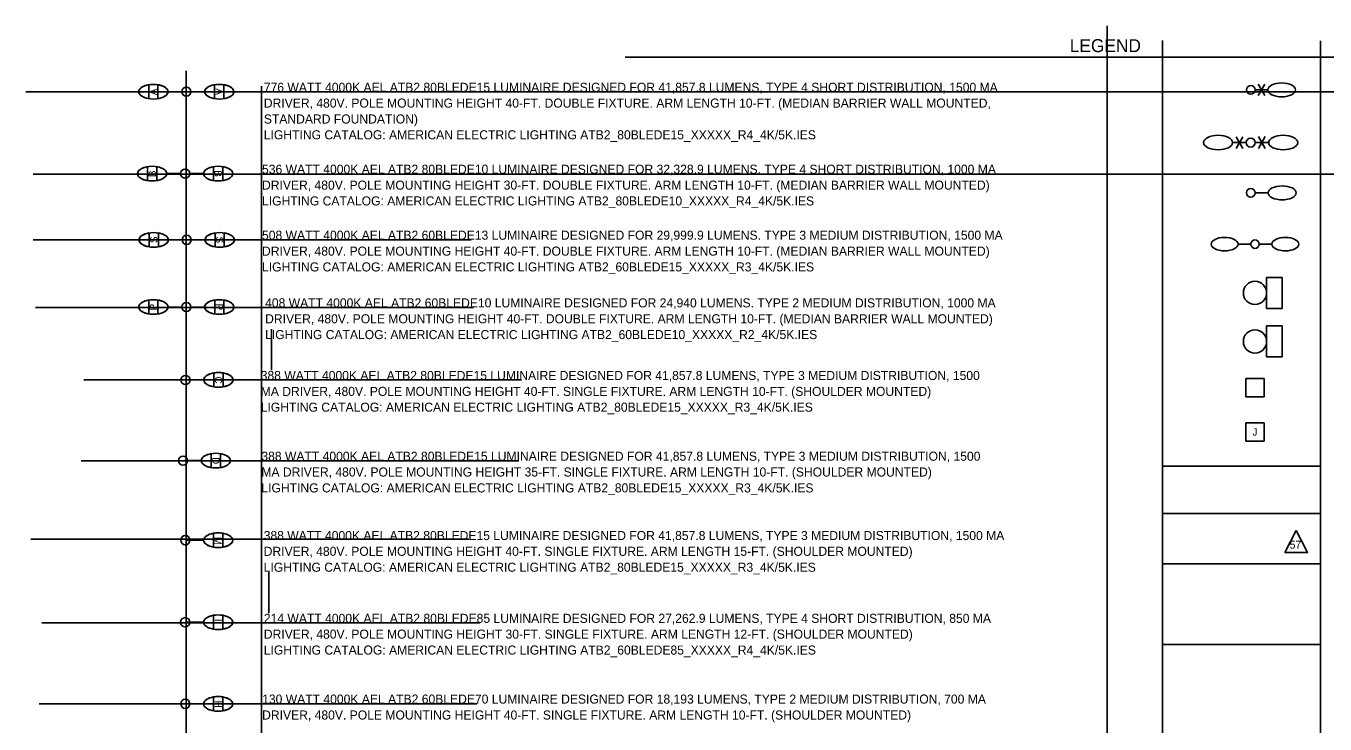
# Model space of a CAD drawing. Extents: x -0.7 to 15.2, y -0.9 to 9.6.
# Drawn here: x -0.65 to 9.38, y 4.21 to 9.6 of the extents above; entities that cross this region are included whole.
import ezdxf

# ---------------------------------------------------------------- set-up
doc = ezdxf.new("R2010")
doc.units = 0
for name, color, linetype in [('ActivePointCell_dp', 7, 'Continuous'), ('AdhocPoint_dp', 7, 'Continuous'), ('Cloud_dp', 7, 'Continuous'), ('Conduit', 7, 'Continuous'), ('JunctBoxA', 7, 'Continuous'), ('LiteCond_ep', 7, 'Continuous'), ('LoadCenter', 7, 'Continuous'), ('LoadCenter_ep', 7, 'Continuous'), ('Miscellaneous1', 7, 'Continuous'), ('Miscellaneous2', 7, 'Continuous'), ('Miscellaneous7', 7, 'Continuous'), ('PoleLight_ep', 7, 'Continuous'), ('ScratchEle_dp', 7, 'Continuous'), ('TextShtNo', 7, 'Continuous'), ('TextTitle', 7, 'Continuous')]:
    doc.layers.add(name, color=color, linetype=linetype)

msp = doc.modelspace()

# ---------------------------------------------------------------- linework, layer by layer
at = {"layer": 'ActivePointCell_dp'}
for p, q in [((7.7, -0.9), (7.7, 9.6)), ((8.126, 9.487), (8.126, 0.725)), ((9.347, 9.484), (9.347, 0.722)), ((0.584, 9.253), (0.584, 0.037)), ((1.164, 0.128), (1.164, 9.134)), ((14.876, 9.092), (-0.655, 9.092)), ((0.584, 9.092), (0.584, 6.27)), ((14.867, 8.456), (-0.599, 8.456)), ((2.784, 7.946), (-0.599, 7.946)), ((2.802, 7.424), (-0.582, 7.424)), ((1.241, 6.941), (1.241, 7.258)), ((3.174, 6.864), (-0.209, 6.864)), ((3.154, 6.24), (-0.229, 6.24)), ((2.766, 5.634), (-0.617, 5.634)), ((1.221, 5.062), (1.221, 5.379)), ((2.853, 4.986), (-0.531, 4.986)), ((2.83, 4.36), (-0.553, 4.36))]:
    msp.add_line(p, q, dxfattribs=at)
at = {"layer": 'Cloud_dp'}
msp.add_lwpolyline([(9.16, 5.7), (9.072, 5.531), (9.248, 5.531)], close=True, dxfattribs=at)
at = {"layer": 'Conduit'}
msp.add_line((8.126, 6.199), (9.347, 6.199), dxfattribs=at)
at = {"layer": 'LiteCond_ep'}
msp.add_line((8.126, 5.831), (9.347, 5.831), dxfattribs=at)
at = {"layer": 'LoadCenter'}
for p, q in [((8.931, 7.042), (8.931, 7.282)), ((8.931, 7.282), (9.051, 7.282)), ((9.051, 7.282), (9.051, 7.042)), ((9.051, 7.042), (8.931, 7.042))]:
    msp.add_line(p, q, dxfattribs=at)
msp.add_circle((8.841, 7.162), 0.09, dxfattribs=at)
at = {"layer": 'LoadCenter_ep'}
for p, q in [((8.931, 7.417), (8.931, 7.657)), ((8.931, 7.657), (9.051, 7.657)), ((9.051, 7.657), (9.051, 7.417)), ((9.051, 7.417), (8.931, 7.417))]:
    msp.add_line(p, q, dxfattribs=at)
msp.add_circle((8.841, 7.537), 0.09, dxfattribs=at)
at = {"layer": 'Miscellaneous1'}
msp.add_line((8.121, 5.443), (9.343, 5.443), dxfattribs=at)
at = {"layer": 'Miscellaneous2'}
for centre in [(0.832, 6.865), (0.812, 6.241), (0.83, 5.626), (0.83, 4.992), (0.83, 4.361)]:
    msp.add_ellipse(centre, major_axis=(-0.113, 0), ratio=0.5, start_param=4.391241, end_param=4.391271, dxfattribs=at)
at = {"layer": 'Miscellaneous7'}
msp.add_line((8.125, 4.821), (9.343, 4.821), dxfattribs=at)
at = {"layer": 'PoleLight_ep'}
for p, q in [((8.916, 9.063), (8.866, 9.149)), ((8.916, 9.149), (8.866, 9.063)), ((8.841, 9.106), (8.941, 9.106)), ((8.695, 8.653), (8.748, 8.744)), ((8.695, 8.744), (8.748, 8.653)), ((8.92, 8.745), (8.868, 8.654)), ((8.92, 8.654), (8.868, 8.745)), ((8.773, 8.699), (8.668, 8.699)), ((8.843, 8.699), (8.947, 8.699)), ((8.841, 8.31), (8.943, 8.31)), ((8.808, 7.914), (8.71, 7.914)), ((8.873, 7.914), (8.971, 7.914))]:
    msp.add_line(p, q, dxfattribs=at)
for centre, radius in [((8.808, 9.106), 0.0333), ((8.808, 8.699), 0.0349), ((8.808, 8.31), 0.0338), ((8.841, 7.914), 0.0326)]:
    msp.add_circle(centre, radius, dxfattribs=at)
for centre, major_axis in [((9.047, 9.106), (0.107, 0)), ((8.556, 8.699), (-0.112, 0)), ((9.059, 8.699), (0.112, 0)), ((9.051, 8.31), (0.108, 0)), ((8.606, 7.914), (-0.104, 0)), ((9.076, 7.914), (0.104, 0))]:
    msp.add_ellipse(centre, major_axis=major_axis, ratio=0.5, dxfattribs=at)
at = {"layer": 'ScratchEle_dp'}
for p, q in [((0.294, 9.038), (0.294, 9.145)), ((0.365, 9.145), (0.365, 9.038)), ((0.803, 9.038), (0.803, 9.145)), ((0.875, 9.145), (0.875, 9.038)), ((0.549, 9.092), (0.443, 9.092)), ((0.62, 9.092), (0.726, 9.092)), ((0.285, 8.405), (0.285, 8.512)), ((0.356, 8.512), (0.356, 8.405)), ((0.54, 8.459), (0.434, 8.459)), ((0.611, 8.459), (0.717, 8.459)), ((0.794, 8.405), (0.794, 8.512)), ((0.866, 8.512), (0.866, 8.405)), ((0.296, 7.894), (0.296, 8.001)), ((0.368, 8.001), (0.368, 7.894)), ((0.551, 7.947), (0.445, 7.947)), ((0.622, 7.947), (0.728, 7.947)), ((0.806, 7.894), (0.806, 8.001)), ((0.877, 8.001), (0.877, 7.894)), ((0.294, 7.374), (0.294, 7.482)), ((0.365, 7.482), (0.365, 7.374)), ((0.549, 7.428), (0.443, 7.428)), ((0.62, 7.428), (0.726, 7.428)), ((0.804, 7.374), (0.804, 7.482)), ((0.875, 7.482), (0.875, 7.374)), ((0.593, 6.864), (0.724, 6.864)), ((0.797, 6.811), (0.797, 6.918)), ((0.797, 6.917), (0.797, 6.811)), ((0.868, 6.918), (0.868, 6.811)), ((0.868, 6.811), (0.868, 6.918)), ((0.573, 6.241), (0.704, 6.241)), ((0.777, 6.187), (0.777, 6.295)), ((0.777, 6.294), (0.777, 6.187)), ((0.848, 6.295), (0.848, 6.187)), ((0.848, 6.187), (0.848, 6.295)), ((0.591, 5.626), (0.722, 5.626)), ((0.794, 5.572), (0.794, 5.68)), ((0.794, 5.679), (0.794, 5.572)), ((0.866, 5.68), (0.866, 5.572)), ((0.866, 5.572), (0.866, 5.68)), ((0.794, 4.938), (0.794, 5.046)), ((0.794, 5.045), (0.794, 4.938)), ((0.865, 5.046), (0.865, 4.938)), ((0.865, 4.938), (0.865, 5.046)), ((0.59, 4.992), (0.721, 4.992)), ((0.591, 4.361), (0.722, 4.361)), ((0.795, 4.307), (0.795, 4.415)), ((0.795, 4.413), (0.795, 4.307)), ((0.866, 4.415), (0.866, 4.307)), ((0.866, 4.307), (0.866, 4.415))]:
    msp.add_line(p, q, dxfattribs=at)
for centre in [(0.584, 9.092), (0.584, 9.092), (0.575, 8.459), (0.575, 8.459), (0.587, 7.947), (0.587, 7.947), (0.584, 7.428), (0.584, 7.428), (0.578, 6.864), (0.578, 6.864), (0.558, 6.241), (0.558, 6.241), (0.576, 5.626), (0.576, 5.626), (0.575, 4.992), (0.575, 4.992), (0.576, 4.361), (0.576, 4.361)]:
    msp.add_circle(centre, 0.0354, dxfattribs=at)
for centre, major_axis in [((0.33, 9.092), (0.113, 0)), ((0.839, 9.092), (0.113, 0)), ((0.32, 8.459), (0.113, 0)), ((0.83, 8.459), (0.113, 0)), ((0.332, 7.947), (0.113, 0)), ((0.842, 7.947), (0.113, 0)), ((0.33, 7.428), (0.113, 0)), ((0.839, 7.428), (0.113, 0)), ((0.832, 6.865), (-0.113, 0)), ((0.812, 6.241), (-0.113, 0)), ((0.83, 5.626), (-0.113, 0)), ((0.83, 4.992), (-0.113, 0)), ((0.83, 4.361), (-0.113, 0))]:
    msp.add_ellipse(centre, major_axis=major_axis, ratio=0.5, dxfattribs=at)
for centre, major_axis, start_param, end_param in [((0.33, 9.092), (0.113, 0), 1.891945, 4.391241), ((0.33, 9.092), (0.113, 0), 0.847605, 1.249648), ((0.33, 9.092), (0.113, 0), 0, 0.847605), ((0.839, 9.092), (0.113, 0), 1.891945, 4.391241), ((0.839, 9.092), (0.113, 0), 0.847605, 1.249648), ((0.839, 9.092), (0.113, 0), 0, 0.847605), ((0.33, 9.092), (0.113, 0), 5.033538, 6.283185), ((0.839, 9.092), (0.113, 0), 5.033538, 6.283185), ((0.32, 8.459), (0.113, 0), 1.891945, 4.391241), ((0.32, 8.459), (0.113, 0), 0.847605, 1.249648), ((0.32, 8.459), (0.113, 0), 5.033538, 6.283185), ((0.32, 8.459), (0.113, 0), 0, 0.847605), ((0.83, 8.459), (0.113, 0), 1.891945, 4.391241), ((0.83, 8.459), (0.113, 0), 0.847605, 1.249648), ((0.83, 8.459), (0.113, 0), 5.033538, 6.283185), ((0.83, 8.459), (0.113, 0), 0, 0.847605), ((0.332, 7.947), (0.113, 0), 1.891945, 4.391241), ((0.332, 7.947), (0.113, 0), 0.847605, 1.249648), ((0.332, 7.947), (0.113, 0), 5.033538, 6.283185), ((0.332, 7.947), (0.113, 0), 0, 0.847605), ((0.842, 7.947), (0.113, 0), 1.891945, 4.391241), ((0.842, 7.947), (0.113, 0), 0.847605, 1.249648), ((0.842, 7.947), (0.113, 0), 5.033538, 6.283185), ((0.842, 7.947), (0.113, 0), 0, 0.847605), ((0.33, 7.428), (0.113, 0), 1.891945, 4.391241), ((0.33, 7.428), (0.113, 0), 0.847605, 1.249648), ((0.33, 7.428), (0.113, 0), 5.033538, 6.283185), ((0.33, 7.428), (0.113, 0), 0, 0.847605), ((0.839, 7.428), (0.113, 0), 1.891945, 4.391241), ((0.839, 7.428), (0.113, 0), 0.847605, 1.249648), ((0.839, 7.428), (0.113, 0), 5.033538, 6.283185), ((0.839, 7.428), (0.113, 0), 0, 0.847605), ((0.832, 6.865), (-0.113, 0), 5.033538, 6.283185), ((0.832, 6.865), (-0.113, 0), 0, 0.847605), ((0.832, 6.865), (-0.113, 0), 4.391271, 5.033538), ((0.832, 6.865), (-0.113, 0), 1.891945, 4.391241), ((0.832, 6.865), (-0.113, 0), 0.847605, 1.249648), ((0.832, 6.865), (-0.113, 0), 1.249648, 1.891946), ((0.812, 6.241), (-0.113, 0), 5.033538, 6.283185), ((0.812, 6.241), (-0.113, 0), 0, 0.847605), ((0.812, 6.241), (-0.113, 0), 4.391271, 5.033538), ((0.812, 6.241), (-0.113, 0), 1.891945, 4.391241), ((0.812, 6.241), (-0.113, 0), 0.847605, 1.249648), ((0.812, 6.241), (-0.113, 0), 1.249648, 1.891946), ((0.83, 5.626), (-0.113, 0), 5.033538, 6.283185), ((0.83, 5.626), (-0.113, 0), 0, 0.847605), ((0.83, 5.626), (-0.113, 0), 4.391271, 5.033538), ((0.83, 5.626), (-0.113, 0), 1.891945, 4.391241), ((0.83, 5.626), (-0.113, 0), 0.847605, 1.249648), ((0.83, 4.992), (-0.113, 0), 5.033538, 6.283185), ((0.83, 4.992), (-0.113, 0), 4.391271, 5.033538), ((0.83, 4.992), (-0.113, 0), 1.891945, 4.391241), ((0.83, 4.992), (-0.113, 0), 0, 0.847605), ((0.83, 4.992), (-0.113, 0), 0.847605, 1.249648), ((0.83, 4.992), (-0.113, 0), 1.249648, 1.891946), ((0.83, 4.361), (-0.113, 0), 4.391271, 5.033538), ((0.83, 4.361), (-0.113, 0), 5.033538, 6.283185), ((0.83, 4.361), (-0.113, 0), 0, 0.847605), ((0.83, 4.361), (-0.113, 0), 0.847605, 1.249648), ((0.83, 4.361), (-0.113, 0), 1.891945, 4.391241), ((0.83, 4.361), (-0.113, 0), 1.249648, 1.891946)]:
    msp.add_ellipse(centre, major_axis=major_axis, ratio=0.5, start_param=start_param, end_param=end_param, dxfattribs=at)
at = {"layer": 'TextShtNo'}
msp.add_line((3.976, 9.358), (12.03, 9.358), dxfattribs=at)
at = {"layer": 'TextTitle'}
for p, q in [((8.77, 6.734), (8.77, 6.875)), ((8.77, 6.875), (8.911, 6.875)), ((8.911, 6.875), (8.911, 6.734)), ((8.911, 6.734), (8.77, 6.734)), ((8.77, 6.533), (8.911, 6.533)), ((8.77, 6.392), (8.77, 6.533)), ((8.911, 6.533), (8.911, 6.392)), ((8.911, 6.392), (8.77, 6.392))]:
    msp.add_line(p, q, dxfattribs=at)

# ---------------------------------------------------------------- texts
at = {"layer": 'AdhocPoint_dp'}
for s, height, p in [('LEGEND', 0.1, (7.41, 9.398)), ('776 WATT 4000K AEL ATB2 80BLEDE15 LUMINAIRE DESIGNED FOR 41,857.8 LUMENS, TYPE 4 SHORT DISTRIBUTION, 1500 MA ', 0.07, (1.183, 9.091)), ('DRIVER, 480V. POLE MOUNTING HEIGHT 40-FT. DOUBLE FIXTURE. ARM LENGTH 10-FT. (MEDIAN BARRIER WALL MOUNTED, ', 0.07, (1.183, 8.969)), ('STANDARD FOUNDATION)', 0.07, (1.183, 8.846)), ('LIGHTING CATALOG: AMERICAN ELECTRIC LIGHTING ATB2_80BLEDE15_XXXXX_R4_4K/5K.IES', 0.07, (1.183, 8.724)), ('536 WATT 4000K AEL ATB2 80BLEDE10 LUMINAIRE DESIGNED FOR 32,328.9 LUMENS. TYPE 4 SHORT DISTRIBUTION, 1000 MA ', 0.07, (1.169, 8.458)), ('DRIVER, 480V. POLE MOUNTING HEIGHT 30-FT. DOUBLE FIXTURE. ARM LENGTH 10-FT. (MEDIAN BARRIER WALL MOUNTED)', 0.07, (1.169, 8.335)), ('LIGHTING CATALOG: AMERICAN ELECTRIC LIGHTING ATB2_80BLEDE10_XXXXX_R4_4K/5K.IES', 0.07, (1.169, 8.213)), ('508 WATT 4000K AEL ATB2 60BLEDE13 LUMINAIRE DESIGNED FOR 29,999.9 LUMENS. TYPE 3 MEDIUM DISTRIBUTION, 1500 MA ', 0.07, (1.169, 7.948)), ('DRIVER, 480V. POLE MOUNTING HEIGHT 40-FT. DOUBLE FIXTURE. ARM LENGTH 10-FT. (MEDIAN BARRIER WALL MOUNTED)', 0.07, (1.169, 7.825)), ('LIGHTING CATALOG: AMERICAN ELECTRIC LIGHTING ATB2_60BLEDE15_XXXXX_R3_4K/5K.IES', 0.07, (1.169, 7.703)), ('408 WATT 4000K AEL ATB2 60BLEDE10 LUMINAIRE DESIGNED FOR 24,940 LUMENS. TYPE 2 MEDIUM DISTRIBUTION, 1000 MA ', 0.07, (1.193, 7.425)), ('DRIVER, 480V. POLE MOUNTING HEIGHT 40-FT. DOUBLE FIXTURE. ARM LENGTH 10-FT. (MEDIAN BARRIER WALL MOUNTED)', 0.07, (1.193, 7.302)), ('LIGHTING CATALOG: AMERICAN ELECTRIC LIGHTING ATB2_60BLEDE10_XXXXX_R2_4K/5K.IES', 0.07, (1.193, 7.18)), ('388 WATT 4000K AEL ATB2 80BLEDE15 LUMINAIRE DESIGNED FOR 41,857.8 LUMENS, TYPE 3 MEDIUM DISTRIBUTION, 1500 ', 0.07, (1.159, 6.864)), ('MA DRIVER, 480V. POLE MOUNTING HEIGHT 40-FT. SINGLE FIXTURE. ARM LENGTH 10-FT. (SHOULDER MOUNTED)', 0.07, (1.159, 6.741)), ('LIGHTING CATALOG: AMERICAN ELECTRIC LIGHTING ATB2_80BLEDE15_XXXXX_R3_4K/5K.IES', 0.07, (1.159, 6.619)), ('388 WATT 4000K AEL ATB2 80BLEDE15 LUMINAIRE DESIGNED FOR 41,857.8 LUMENS, TYPE 3 MEDIUM DISTRIBUTION, 1500 ', 0.07, (1.164, 6.24)), ('MA DRIVER, 480V. POLE MOUNTING HEIGHT 35-FT. SINGLE FIXTURE. ARM LENGTH 10-FT. (SHOULDER MOUNTED)', 0.07, (1.164, 6.118)), ('LIGHTING CATALOG: AMERICAN ELECTRIC LIGHTING ATB2_80BLEDE15_XXXXX_R3_4K/5K.IES', 0.07, (1.164, 5.995)), ('388 WATT 4000K AEL ATB2 80BLEDE15 LUMINAIRE DESIGNED FOR 41,857.8 LUMENS, TYPE 3 MEDIUM DISTRIBUTION, 1500 MA ', 0.07, (1.182, 5.627)), ('DRIVER, 480V. POLE MOUNTING HEIGHT 40-FT. SINGLE FIXTURE. ARM LENGTH 15-FT. (SHOULDER MOUNTED)', 0.07, (1.182, 5.505)), ('LIGHTING CATALOG: AMERICAN ELECTRIC LIGHTING ATB2_80BLEDE15_XXXXX_R3_4K/5K.IES', 0.07, (1.182, 5.382)), ('214 WATT 4000K AEL ATB2 80BLEDE85 LUMINAIRE DESIGNED FOR 27,262.9 LUMENS, TYPE 4 SHORT DISTRIBUTION, 850 MA ', 0.07, (1.183, 4.987)), ('DRIVER, 480V. POLE MOUNTING HEIGHT 30-FT. SINGLE FIXTURE. ARM LENGTH 12-FT. (SHOULDER MOUNTED)', 0.07, (1.183, 4.865)), ('LIGHTING CATALOG: AMERICAN ELECTRIC LIGHTING ATB2_60BLEDE85_XXXXX_R4_4K/5K.IES', 0.07, (1.183, 4.742)), ('130 WATT 4000K AEL ATB2 60BLEDE70 LUMINAIRE DESIGNED FOR 18,193 LUMENS, TYPE 2 MEDIUM DISTRIBUTION, 700 MA ', 0.07, (1.17, 4.363)), ('DRIVER, 480V. POLE MOUNTING HEIGHT 40-FT. SINGLE FIXTURE. ARM LENGTH 10-FT. (SHOULDER MOUNTED)', 0.07, (1.17, 4.24))]:
    msp.add_text(s, height=height, dxfattribs=at).set_placement(p)
at = {"layer": 'Cloud_dp'}
msp.add_text('57', height=0.06, dxfattribs=at).set_placement((9.109, 5.561))
at = {"layer": 'JunctBoxA'}
msp.add_text('J', height=0.0563, dxfattribs=at).set_placement((8.822, 6.434))
at = {"layer": 'TextShtNo'}
for s, rotation, p in [('A', 90, (0.358, 9.065)), ('A', 270, (0.811, 9.118)), ('B', 90, (0.349, 8.432)), ('B', 270, (0.801, 8.485)), ('S', 90, (0.361, 7.922)), ('S', 270, (0.813, 7.973)), ('P', 90, (0.358, 7.402)), ('P', 270, (0.811, 7.454)), ('C', 270, (0.804, 6.891)), ('D', 270, (0.784, 6.268)), ('M', 270, (0.801, 5.653)), ('I', 270, (0.803, 5.018)), ('H', 270, (0.802, 4.387))]:
    msp.add_text(s, height=0.0572, rotation=rotation, dxfattribs=at).set_placement(p)

doc.saveas('drawing.dxf')
